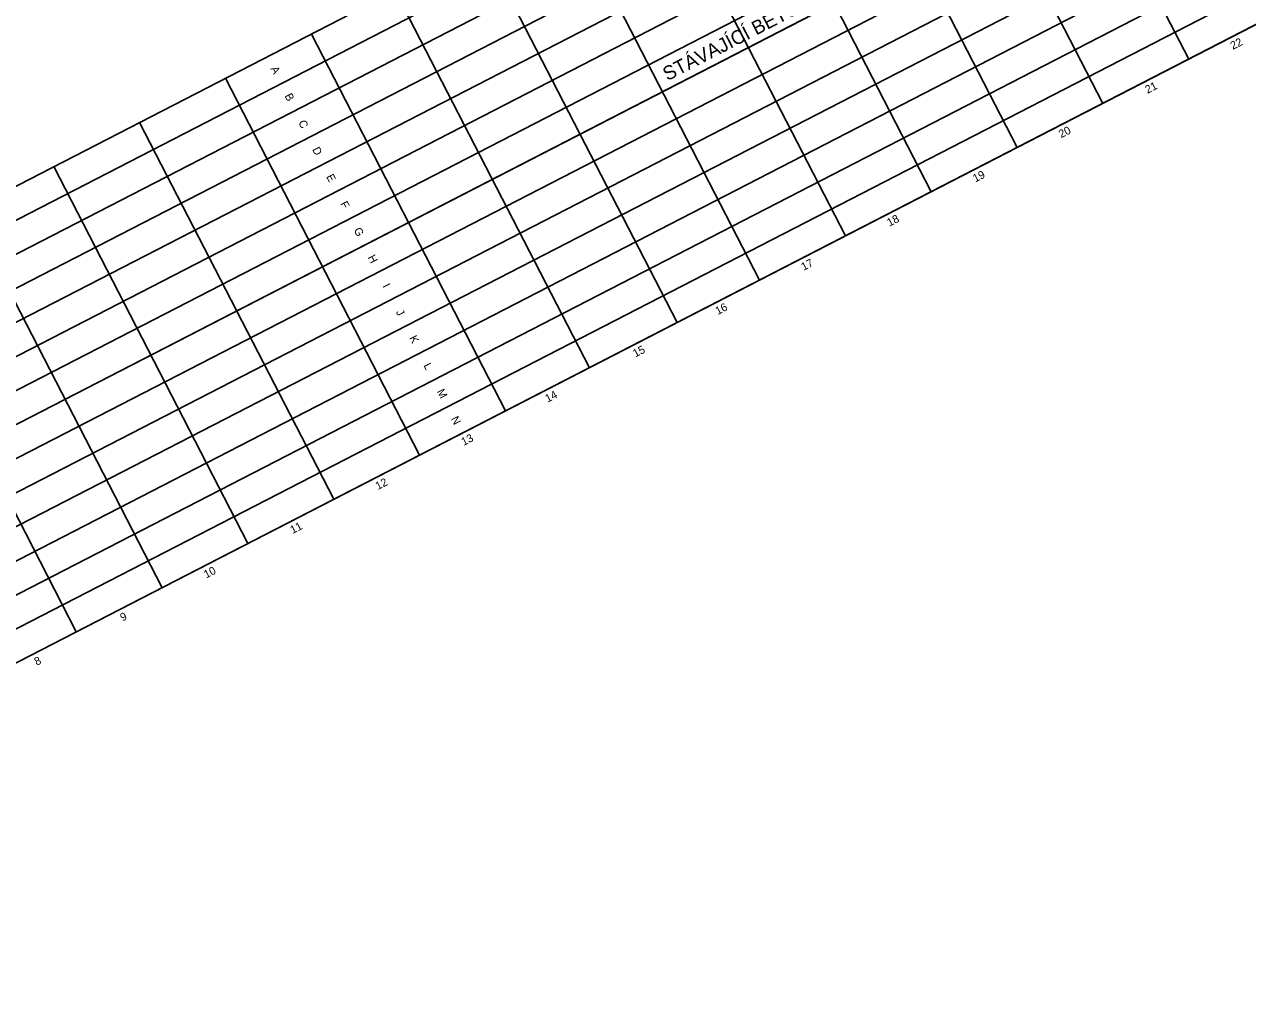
# Model space of a CAD drawing. Extents: x -886320 to -884760, y -1024172 to -1023483.
# Drawn here: x -885926.3 to -885773.4, y -1024171.6 to -1024051.4 of the extents above; entities that cross this region are included whole.
import ezdxf

# ---------------------------------------------------------------- set-up
doc = ezdxf.new("R2010")
doc.units = 0
for name, color, linetype in [('AGA__Netisknout', 7, 'Continuous'), ('Stavajici_betonova_draha', 7, 'Continuous'), ('Stavajici_betonova_draha_osa', 7, 'Continuous'), ('Stavajici_betonova_draha_popis', 7, 'Continuous'), ('Stavajici_betonova_draha_Popis desky', 7, 'Continuous'), ('Stavajici_betonova_draha_Spára', 7, 'Continuous')]:
    doc.layers.add(name, color=color, linetype=linetype)

msp = doc.modelspace()

# ---------------------------------------------------------------- linework, layer by layer
at = {"layer": 'AGA__Netisknout'}
msp.add_line((-886017.78, -1024147.99), (-884773.13, -1023507.02), dxfattribs=at)
at = {"layer": 'Stavajici_betonova_draha'}
for p, q in [((-886029.69, -1024124.32), (-884785.04, -1023483.35)), ((-886029.69, -1024124.32), (-884785.04, -1023483.35)), ((-886005.42, -1024171.44), (-884760.77, -1023530.47)), ((-886005.42, -1024171.44), (-884760.77, -1023530.47))]:
    msp.add_line(p, q, dxfattribs=at)
at = {"layer": 'Stavajici_betonova_draha_osa'}
msp.add_line((-886017.55, -1024147.88), (-884772.9, -1023506.91), dxfattribs=at)
at = {"layer": 'Stavajici_betonova_draha_Spára'}
for p, q in [((-886029.91, -1024124.43), (-884785.26, -1023483.46)), ((-886028.18, -1024127.8), (-884783.53, -1023486.82)), ((-886026.44, -1024131.16), (-884781.79, -1023490.19)), ((-886024.71, -1024134.53), (-884780.06, -1023493.56)), ((-886022.98, -1024137.89), (-884778.33, -1023496.92)), ((-886021.24, -1024141.26), (-884776.59, -1023500.29)), ((-886019.51, -1024144.63), (-884774.86, -1023503.65)), ((-886016.04, -1024151.36), (-884771.39, -1023510.39)), ((-886014.31, -1024154.72), (-884769.66, -1023513.75)), ((-886012.58, -1024158.09), (-884767.93, -1023517.12)), ((-886010.84, -1024161.46), (-884766.19, -1023520.48)), ((-886009.11, -1024164.82), (-884764.46, -1023523.85)), ((-886007.38, -1024168.19), (-884762.73, -1023527.21)), ((-886005.64, -1024171.55), (-884760.99, -1023530.58)), ((-885805.02, -1024008.62), (-885780.75, -1024055.74)), ((-885815.75, -1024014.14), (-885791.48, -1024061.27)), ((-885826.48, -1024019.67), (-885802.21, -1024066.79)), ((-885837.21, -1024025.19), (-885812.94, -1024072.32)), ((-885847.94, -1024030.72), (-885823.67, -1024077.84)), ((-885858.67, -1024036.25), (-885834.4, -1024083.37)), ((-885868.96, -1024041.55), (-885844.7, -1024088.67)), ((-885879.94, -1024047.2), (-885855.67, -1024094.32)), ((-885890.42, -1024052.6), (-885866.16, -1024099.72)), ((-885901.15, -1024058.12), (-885876.89, -1024105.25)), ((-885911.88, -1024063.65), (-885887.61, -1024110.77)), ((-885922.61, -1024069.17), (-885898.34, -1024116.3)), ((-885933.34, -1024074.7), (-885909.07, -1024121.82)), ((-885944.07, -1024080.23), (-885919.8, -1024127.35))]:
    msp.add_line(p, q, dxfattribs=at)

# ---------------------------------------------------------------- texts
at = {"layer": 'Stavajici_betonova_draha_popis'}
msp.add_text('STÁVAJÍCÍ BETONOVÁ DRÁHA 1400 × 52,8 m', height=1.75, rotation=27.2477, dxfattribs=at).set_placement((-885845.92, -1024058.51))
at = {"layer": 'Stavajici_betonova_draha_Popis desky'}
for s, rotation, p in [('22', 27.2477, (-885775.24, -1024054.59)), ('A', 297.2477, (-885895.54, -1024056.93)), ('B', 297.2477, (-885893.79, -1024060.32)), ('21', 27.2477, (-885785.9, -1024060.08)), ('C', 297.2477, (-885892.08, -1024063.66)), ('20', 27.2477, (-885796.7, -1024065.64)), ('D', 297.2477, (-885890.34, -1024067.03)), ('E', 297.2477, (-885888.59, -1024070.42)), ('19', 27.2477, (-885807.43, -1024071.17)), ('F', 297.2477, (-885886.85, -1024073.81)), ('18', 27.2477, (-885818.16, -1024076.69)), ('G', 297.2477, (-885885.15, -1024077.1)), ('H', 297.2477, (-885883.4, -1024080.51)), ('17', 27.2477, (-885828.89, -1024082.22)), ('I', 297.2477, (-885881.55, -1024084.1)), ('J', 297.2477, (-885879.88, -1024087.35)), ('16', 27.2477, (-885839.62, -1024087.74)), ('K', 297.2477, (-885878.21, -1024090.59)), ('15', 27.2477, (-885849.92, -1024093.05)), ('L', 297.2477, (-885876.43, -1024094.03)), ('M', 297.2477, (-885874.76, -1024097.28)), ('14', 27.2477, (-885860.89, -1024098.69)), ('N', 297.2477, (-885873, -1024100.7)), ('13', 27.2477, (-885871.38, -1024104.1)), ('12', 27.2477, (-885882.1, -1024109.62)), ('11', 27.2477, (-885892.76, -1024115.11)), ('10', 27.2477, (-885903.56, -1024120.67)), ('9', 27.2477, (-885914.01, -1024126.05)), ('8', 27.2477, (-885924.74, -1024131.58))]:
    msp.add_text(s, height=1, rotation=rotation, dxfattribs=at).set_placement(p)

doc.saveas('drawing.dxf')
